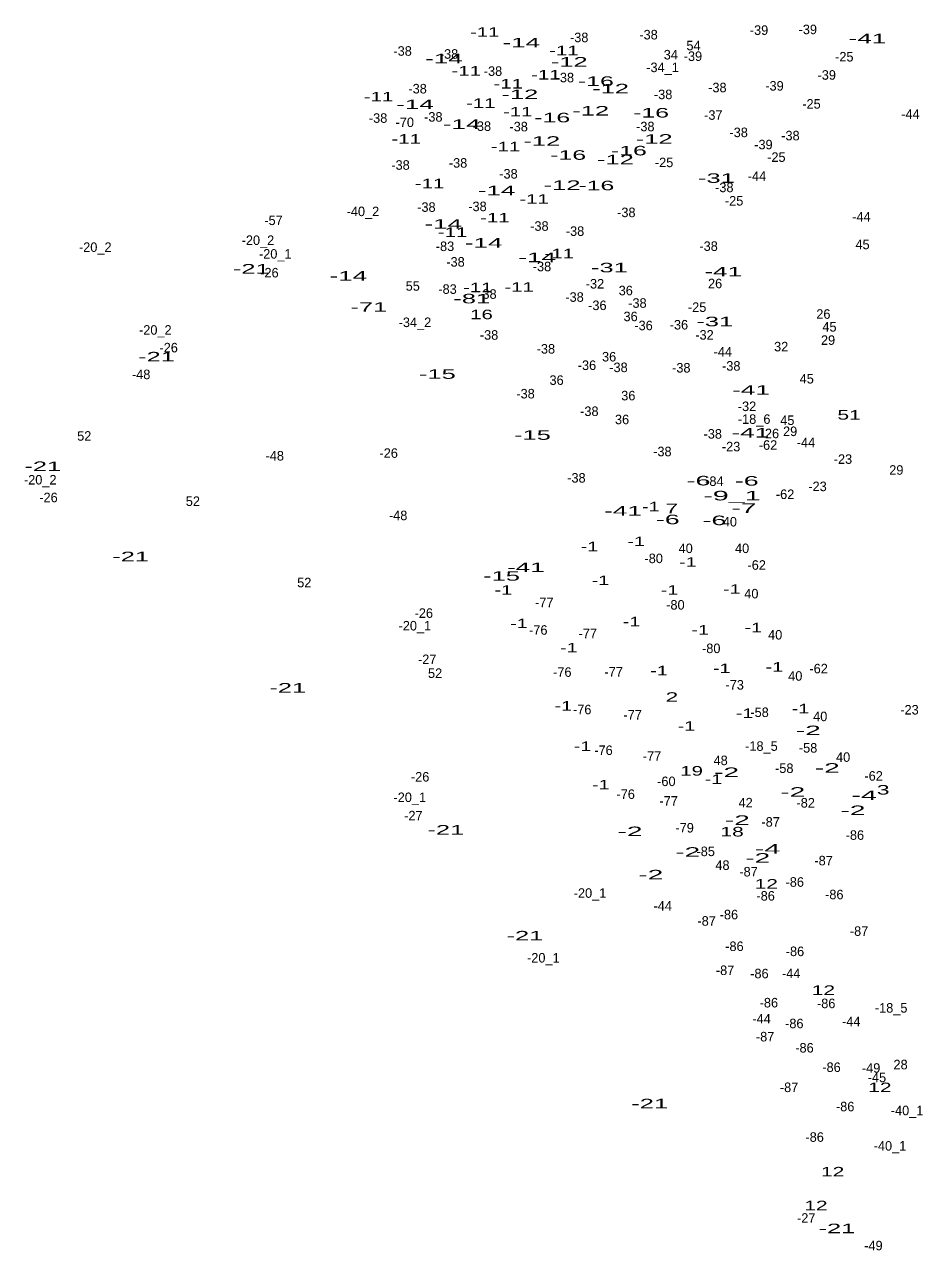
# Model space of a CAD drawing. Extents: x -657046 to -655830, y -1000534 to -999433.
# Drawn here: x -657046 to -656670, y -1000469 to -999955 of the extents above; entities that cross this region are included whole.
import ezdxf
from ezdxf.enums import TextEntityAlignment as Align

# ---------------------------------------------------------------- set-up
doc = ezdxf.new("R2010")
doc.units = 0
doc.header["$LTSCALE"] = 1.6
doc.layers.add('24', color=7, linetype='Continuous')

msp = doc.modelspace()

# ---------------------------------------------------------------- texts
at = {"layer": '24'}
for s, width, p in [('-11', 1.6, (-656852.577, -999959.82)), ('-14', 2.05, (-656837.226, -999964.27)), ('-41', 2.05, (-656691.836, -999962.54)), ('-14', 2.05, (-656869.696, -999970.97)), ('-11', 1.6, (-656819.327, -999967.56)), ('-11', 1.6, (-656860.317, -999976.09)), ('-12', 2, (-656817.061, -999972.33)), ('-11', 1.6, (-656842.687, -999981.54)), ('-11', 1.6, (-656826.887, -999977.76)), ('-16', 1.95, (-656805.875, -999980.43)), ('-11', 1.6, (-656897.157, -999986.96)), ('-12', 2, (-656837.811, -999986)), ('-12', 2, (-656799.711, -999983.58)), ('-14', 2.05, (-656881.816, -999990.17)), ('-11', 1.6, (-656854.217, -999989.67)), ('-11', 1.6, (-656838.717, -999993.28)), ('-16', 1.95, (-656824.195, -999995.75)), ('-12', 2, (-656808.051, -999992.88)), ('-16', 1.95, (-656782.705, -999993.71)), ('-14', 2.05, (-656862.236, -999998.51)), ('-11', 1.6, (-656885.527, -1000004.7)), ('-11', 1.6, (-656843.837, -1000007.9)), ('-12', 2, (-656828.601, -1000005.59)), ('-12', 2, (-656781.391, -1000004.72)), ('-16', 1.95, (-656817.505, -1000011.46)), ('-16', 1.95, (-656792.015, -1000009.62)), ('-12', 2, (-656797.681, -1000013.35)), ('-11', 1.6, (-656875.727, -1000023.41)), ('-31', 2, (-656755.271, -1000021.15)), ('-14', 2.05, (-656847.596, -1000026.34)), ('-12', 2, (-656820.071, -1000024.11)), ('-16', 1.95, (-656805.685, -1000024.26)), ('-11', 1.6, (-656831.817, -1000029.91)), ('-11', 1.6, (-656848.297, -1000037.77)), ('-14', 2.05, (-656869.976, -1000040.4)), ('-11', 1.6, (-656866.037, -1000043.87)), ('-14', 2.05, (-656853.016, -1000048.35)), ('-11', 1.6, (-656821.247, -1000052.8)), ('-21', 2, (-656950.601, -1000059.24)), ('-14', 2.05, (-656830.536, -1000054.46)), ('-31', 2, (-656800.201, -1000058.72)), ('-14', 2.05, (-656909.816, -1000062.22)), ('-41', 2.05, (-656752.396, -1000060.41)), ('-11', 1.6, (-656855.467, -1000067.06)), ('-11', 1.6, (-656838.117, -1000066.86)), ('-81', 2, (-656858.011, -1000071.75)), ('-71', 2, (-656901.215, -1000075.3)), ('16', 1.6, (-656853.913, -1000078.39)), ('-31', 2, (-656755.951, -1000081.35)), ('-21', 2, (-656990.391, -1000096.13)), ('-15', 2, (-656872.451, -1000103.43)), ('-41', 2.05, (-656740.746, -1000110.11)), ('51', 1.65, (-656699.537, -1000120.56)), ('-15', 2, (-656832.511, -1000129.03)), ('-41', 2.05, (-656741.036, -1000128.07)), ('-21', 2, (-657038.141, -1000142.15)), ('-6', 2.1, (-656762.779, -1000148.18)), ('-6', 2.1, (-656742.519, -1000148.28)), ('-9_1', 2.25, (-656748.757, -1000154.47)), ('-41', 2.05, (-656794.506, -1000160.88)), ('-1', 1.55, (-656782.831, -1000159.07)), ('7', 1.8, (-656774.006, -1000159.85)), ('-7', 2.2, (-656743.719, -1000159.74)), ('-6', 2.1, (-656775.679, -1000164.47)), ('-6', 2.1, (-656756.099, -1000164.86)), ('-1', 1.55, (-656808.591, -1000175.81)), ('-1', 1.55, (-656788.981, -1000173.69)), ('-21', 2, (-657001.251, -1000180.02)), ('-1', 1.55, (-656767.251, -1000182.34)), ('-15', 2, (-656845.501, -1000188.19)), ('-41', 2.05, (-656835.266, -1000184.57)), ('-1', 1.55, (-656803.971, -1000190.04)), ('-1', 1.55, (-656844.731, -1000194.07)), ('-1', 1.55, (-656774.951, -1000194.08)), ('-1', 1.55, (-656748.801, -1000193.69)), ('-1', 1.55, (-656838.191, -1000208.11)), ('-1', 1.55, (-656790.901, -1000207.35)), ('-1', 1.55, (-656762.071, -1000210.81)), ('-1', 1.55, (-656739.771, -1000209.85)), ('-1', 1.55, (-656817.241, -1000218.31)), ('-1', 1.55, (-656779.371, -1000227.92)), ('-1', 1.55, (-656753.031, -1000226.96)), ('-1', 1.55, (-656730.931, -1000226.38)), ('-21', 2, (-656935.261, -1000235.16)), ('2', 1.8, (-656773.951, -1000239.04)), ('-1', 1.55, (-656819.551, -1000242.73)), ('-1', 1.55, (-656719.971, -1000243.88)), ('-1', 1.55, (-656743.421, -1000245.81)), ('-1', 1.55, (-656767.841, -1000251.19)), ('-2', 2.2, (-656716.664, -1000253.04)), ('-1', 1.55, (-656811.471, -1000259.66)), ('19', 1.6, (-656765.683, -1000270.03)), ('-2', 2.2, (-656750.974, -1000270.63)), ('-2', 2.2, (-656708.684, -1000268.81)), ('-1', 1.55, (-656756.491, -1000273.5)), ('-1', 1.55, (-656803.791, -1000275.81)), ('-2', 2.2, (-656723.194, -1000278.9)), ('-4', 2.25, (-656693.2, -1000280.28)), ('3', 1.8, (-656685.241, -1000277.98)), ('-2', 2.2, (-656746.464, -1000290.72)), ('-2', 2.2, (-656697.914, -1000286.6)), ('-21', 2, (-656868.881, -1000294.78)), ('-2', 2.2, (-656791.534, -1000295.44)), ('18', 1.65, (-656748.687, -1000295.57)), ('-2', 2.2, (-656767.314, -1000304.1)), ('-2', 2.2, (-656737.904, -1000306.6)), ('-4', 2.25, (-656733.77, -1000302.78)), ('-2', 2.2, (-656782.794, -1000313.61)), ('12', 1.65, (-656734.327, -1000317.48)), ('-21', 2, (-656835.681, -1000339.24)), ('12', 1.65, (-656710.337, -1000362.1)), ('12', 1.65, (-656686.627, -1000402.93)), ('-21', 2, (-656783.281, -1000409.73)), ('12', 1.65, (-656706.477, -1000438.33)), ('12', 1.65, (-656713.477, -1000452.52)), ('-21', 2, (-656704.661, -1000462.15))]:
    msp.add_text(s, height=4, dxfattribs=dict(at, width=width)).set_placement(p, align=Align.CENTER)
for s, p in [('-38', (-656783.765, -999960.93)), ('-39', (-656737.37, -999959.02)), ('-39', (-656716.9, -999958.73)), ('-38', (-656812.885, -999962.09)), ('54', (-656764.881, -999965.51)), ('-38', (-656887.045, -999967.78)), ('-38', (-656867.545, -999969.04)), ('34', (-656774.411, -999969.34)), ('-39', (-656765.13, -999969.97)), ('-25', (-656701.555, -999970.19)), ('-38', (-656849.085, -999976.23)), ('-34_1', (-656777.9, -999974.66)), ('-38', (-656818.905, -999978.94)), ('-39', (-656730.87, -999982.42)), ('-39', (-656708.94, -999977.85)), ('-38', (-656880.745, -999983.61)), ('-38', (-656777.645, -999986.01)), ('-38', (-656754.855, -999983.12)), ('-25', (-656715.335, -999990)), ('-38', (-656897.335, -999995.94)), ('-70', (-656886.144, -999997.72)), ('-38', (-656874.145, -999995.45)), ('-37', (-656756.561, -999994.67)), ('-44', (-656673.783, -999994.29)), ('-38', (-656853.755, -999999.34)), ('-38', (-656838.315, -999999.53)), ('-38', (-656785.125, -999999.5)), ('-38', (-656745.925, -1000001.95)), ('-39', (-656735.53, -1000007.08)), ('-38', (-656724.185, -1000003.31)), ('-25', (-656730.085, -1000012.33)), ('-38', (-656887.915, -1000015.65)), ('-38', (-656863.755, -1000014.78)), ('-25', (-656777.245, -1000014.56)), ('-38', (-656842.595, -1000019.34)), ('-44', (-656738.233, -1000020.31)), ('-38', (-656751.945, -1000025.06)), ('-38', (-656877.045, -1000033.32)), ('-38', (-656855.605, -1000033.03)), ('-25', (-656747.835, -1000030.68)), ('-57', (-656941.261, -1000038.88)), ('-40_2', (-656903.711, -1000035.13)), ('-38', (-656793.095, -1000035.54)), ('-44', (-656694.363, -1000037.39)), ('-38', (-656829.595, -1000041.28)), ('-38', (-656814.635, -1000043.41)), ('-20_2', (-656947.796, -1000047.24)), ('45', (-656693.901, -1000049.01)), ('-20_2', (-657016.116, -1000050.15)), ('-20_1', (-656940.52, -1000052.97)), ('-83', (-656869.245, -1000049.78)), ('-38', (-656758.545, -1000049.72)), ('-38', (-656864.825, -1000056.33)), ('-38', (-656828.515, -1000058.27)), ('-26', (-656942.97, -1000060.87)), ('55', (-656882.777, -1000066.44)), ('-83', (-656868.175, -1000067.75)), ('-38', (-656851.425, -1000069.83)), ('-32', (-656806.265, -1000065.52)), ('36', (-656793.333, -1000068.35)), ('26', (-656755.813, -1000065.4)), ('-38', (-656814.835, -1000071.09)), ('-36', (-656805.26, -1000074.57)), ('-38', (-656788.435, -1000073.6)), ('36', (-656791.293, -1000079.24)), ('-25', (-656763.365, -1000075.33)), ('26', (-656710.343, -1000078.22)), ('-20_2', (-656990.886, -1000084.91)), ('-34_2', (-656881.867, -1000081.7)), ('-36', (-656785.86, -1000083.02)), ('-36', (-656771.01, -1000082.72)), ('45', (-656707.791, -1000083.6)), ('-38', (-656850.745, -1000087.01)), ('-32', (-656760.265, -1000086.98)), ('29', (-656708.383, -1000089.17)), ('-26', (-656985.28, -1000092.33)), ('-38', (-656826.875, -1000092.84)), ('-44', (-656752.593, -1000094.09)), ('32', (-656728.067, -1000091.91)), ('-36', (-656809.63, -1000099.72)), ('36', (-656800.323, -1000096.15)), ('-38', (-656796.395, -1000100.61)), ('-38', (-656770.005, -1000100.79)), ('-38', (-656749.035, -1000100.01)), ('-48', (-656996.839, -1000103.56)), ('36', (-656822.383, -1000105.97)), ('45', (-656717.321, -1000105.39)), ('-38', (-656835.415, -1000111.67)), ('36', (-656792.263, -1000112.48)), ('-38', (-656808.625, -1000119.05)), ('-32', (-656742.415, -1000116.97)), ('36', (-656794.883, -1000122.49)), ('-18_6', (-656739.412, -1000122.34)), ('45', (-656725.481, -1000122.82)), ('52', (-657020.737, -1000129.42)), ('-38', (-656756.805, -1000128.55)), ('26', (-656731.913, -1000128.37)), ('29', (-656724.313, -1000127.47)), ('-26', (-656892.89, -1000136.6)), ('-38', (-656777.955, -1000135.95)), ('-23', (-656749.105, -1000133.89)), ('-62', (-656733.59, -1000133.22)), ('-44', (-656717.653, -1000132.15)), ('-48', (-656940.739, -1000137.73)), ('-23', (-656702.125, -1000139.13)), ('-38', (-656814.055, -1000147.01)), ('29', (-656679.713, -1000143.7)), ('-20_2', (-657039.216, -1000147.81)), ('-84', (-656756.129, -1000148.41)), ('-23', (-656712.805, -1000150.59)), ('-26', (-657035.75, -1000155.24)), ('52', (-656975.117, -1000156.8)), ('-62', (-656726.42, -1000153.9)), ('-48', (-656888.919, -1000162.78)), ('40', (-656749.615, -1000165.43)), ('40', (-656768.155, -1000176.59)), ('40', (-656744.475, -1000176.59)), ('-80', (-656781.609, -1000180.82)), ('-62', (-656738.35, -1000183.6)), ('52', (-656928.337, -1000190.97)), ('40', (-656740.585, -1000195.62)), ('-26', (-656878.14, -1000203.79)), ('-77', (-656827.535, -1000199.35)), ('-80', (-656772.489, -1000200.33)), ('-20_1', (-656881.91, -1000209.09)), ('-76', (-656830.055, -1000210.88)), ('-77', (-656809.285, -1000212.36)), ('40', (-656730.595, -1000212.9)), ('-80', (-656757.439, -1000218.59)), ('-27', (-656876.701, -1000223.2)), ('52', (-656873.407, -1000229.03)), ('-76', (-656819.965, -1000228.55)), ('-77', (-656798.415, -1000228.48)), ('-62', (-656712.34, -1000227.1)), ('-73', (-656747.591, -1000233.92)), ('40', (-656722.145, -1000230.18)), ('-76', (-656811.615, -1000244.28)), ('-23', (-656674.175, -1000244.37)), ('-77', (-656790.455, -1000246.53)), ('-58', (-656737.145, -1000245.43)), ('40', (-656711.665, -1000247.17)), ('-18_5', (-656736.356, -1000259.62)), ('-58', (-656716.765, -1000260.38)), ('-76', (-656802.685, -1000261.37)), ('-77', (-656782.305, -1000263.82)), ('40', (-656702.055, -1000264.25)), ('48', (-656753.481, -1000265.64)), ('-58', (-656726.765, -1000268.92)), ('-26', (-656879.69, -1000272.52)), ('-60', (-656776.284, -1000274.43)), ('-62', (-656689.25, -1000272.15)), ('-76', (-656793.365, -1000279.81)), ('-20_1', (-656884.04, -1000281.13)), ('-77', (-656775.315, -1000282.65)), ('42', (-656742.991, -1000283.39)), ('-82', (-656717.785, -1000283.44)), ('-27', (-656882.521, -1000288.83)), ('-79', (-656768.615, -1000293.91)), ('-87', (-656732.491, -1000291.47)), ('-86', (-656697.12, -1000296.99)), ('-85', (-656759.765, -1000303.83)), ('48', (-656752.721, -1000309.61)), ('-87', (-656710.251, -1000307.71)), ('-87', (-656741.771, -1000312.37)), ('-86', (-656722.37, -1000316.69)), ('-20_1', (-656808.34, -1000321.33)), ('-86', (-656705.76, -1000321.94)), ('-44', (-656777.823, -1000326.72)), ('-86', (-656734.59, -1000322.51)), ('-86', (-656750.02, -1000330.37)), ('-87', (-656759.371, -1000333.05)), ('-87', (-656695.351, -1000337.31)), ('-86', (-656747.7, -1000343.68)), ('-86', (-656722.27, -1000345.81)), ('-20_1', (-656827.95, -1000348.51)), ('-87', (-656751.631, -1000353.76)), ('-86', (-656737.21, -1000355.13)), ('-44', (-656723.863, -1000355.07)), ('-86', (-656733.24, -1000367.36)), ('-86', (-656709.17, -1000367.66)), ('-18_5', (-656681.876, -1000369.54)), ('-44', (-656736.283, -1000374.1)), ('-86', (-656722.55, -1000376.1)), ('-44', (-656698.633, -1000375.27)), ('-87', (-656734.811, -1000381.62)), ('-86', (-656718.28, -1000386.3)), ('28', (-656677.927, -1000393.35)), ('-86', (-656706.93, -1000394.45)), ('-49', (-656690.305, -1000394.78)), ('-45', (-656687.849, -1000398.77)), ('-87', (-656724.751, -1000402.9)), ('-86', (-656701.2, -1000410.97)), ('-40_1', (-656675.194, -1000412.62)), ('-86', (-656714.01, -1000423.78)), ('-40_1', (-656682.384, -1000427.48)), ('-27', (-656717.541, -1000457.77)), ('-49', (-656689.335, -1000469.35))]:
    msp.add_text(s, height=4, dxfattribs=at).set_placement(p, align=Align.CENTER)

doc.saveas('drawing.dxf')
